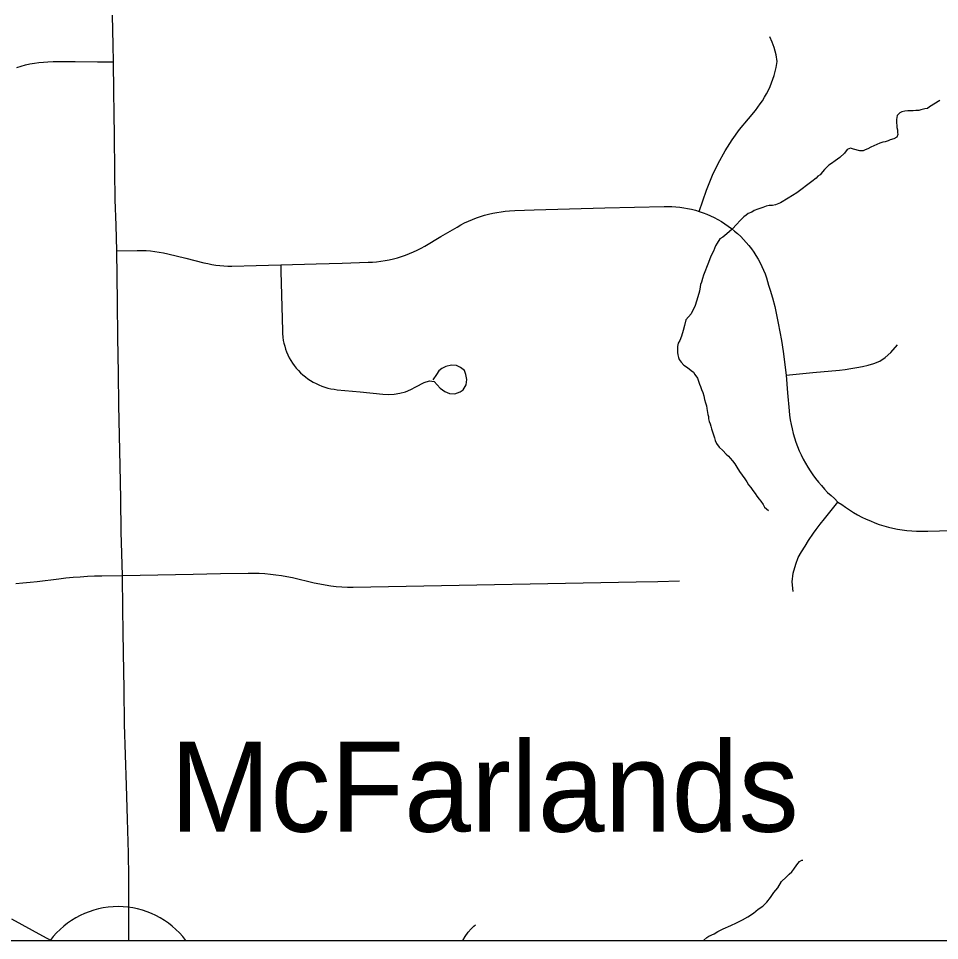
# Model space of a CAD drawing. Extents: x 103424 to 286016, y 38711 to 110967.
# Drawn here: x 108261 to 112556, y 38711 to 43011 of the extents above; entities that cross this region are included whole.
import ezdxf

# ---------------------------------------------------------------- set-up
doc = ezdxf.new("R2010")
doc.units = 0
for name, color, linetype in [('GM_X_Corporation', 7, 'Continuous'), ('GM_X_County_Road', 7, 'Continuous'), ('GM_X_Minor_River', 7, 'Continuous'), ('GM_X_State_Route', 7, 'Continuous'), ('GM_X_Township_Road', 7, 'Continuous'), ('GM_X_Unincorporated_Text', 7, 'Continuous'), ('GM_X_US_Shield', 7, 'Continuous')]:
    doc.layers.add(name, color=color, linetype=linetype)

msp = doc.modelspace()

# ---------------------------------------------------------------- linework, layer by layer
at = {"layer": 'GM_X_Corporation'}
for points in [[(103423.7, 96534.8), (103423.7, 38711.2), (175679.7, 38711.2), (175679.7, 110967.2), (119699, 110967.2), (119716.9, 106542.5), (119719.8, 106322.8), (119720.8, 106006.3), (119709.7, 99445.7), (119706.4, 99064.2), (119663.9, 96690), (117026.4, 96688.2), (115542.1, 96665), (105081.7, 96574.5)], [(103423.7, 43132.7), (103423.7, 38711.2), (119963.5, 38711.2), (119934.2, 43543), (116952, 43470.9), (108691.3, 43264.4)]]:
    msp.add_lwpolyline(points, close=True, dxfattribs=at)
at = {"layer": 'GM_X_County_Road'}
msp.add_lwpolyline([(108228, 38812.2), (108373.1, 38733.4), (108414, 38711.2)], dxfattribs=at)
at = {"layer": 'GM_X_Minor_River'}
for points in [[(112556.9, 42628.6), (112508.9, 42599.5), (112499, 42591.3), (112486.9, 42589.1), (112468.8, 42584.7), (112458.8, 42582.6), (112444.6, 42582.3), (112432.6, 42580.1), (112420.5, 42579.9), (112408.3, 42579.7), (112394.2, 42579.5), (112380.2, 42575.2), (112370.2, 42571), (112358.3, 42558.7), (112354.5, 42540.4), (112354.8, 42524.3), (112357, 42512.2), (112357.2, 42502.1), (112359.4, 42492), (112359.6, 42479.9), (112361.8, 42469.8), (112355.9, 42457.6), (112341.9, 42449.3), (112325.9, 42445), (112315.9, 42440.8), (112301.8, 42436.5), (112291.7, 42434.3), (112277.7, 42430.1), (112263.7, 42423.8), (112249.7, 42417.5), (112235.6, 42411.2), (112221.7, 42402.9), (112209.6, 42398.7), (112199.6, 42394.4), (112183.5, 42394.2), (112155.1, 42401.8), (112140.9, 42405.6), (112124.8, 42399.3), (112113, 42382.9), (112091.2, 42362.4), (112069.2, 42347.9), (112051.3, 42335.4), (112039.3, 42327.2), (112019.5, 42306.6), (112009.5, 42296.4), (111999.7, 42282.1), (111987.7, 42275.8), (111979.8, 42265.6), (111959.9, 42251.1), (111890.1, 42197.4), (111850.2, 42172.5), (111814.2, 42151.7), (111790.2, 42141.2), (111776.1, 42139), (111762, 42138.8), (111747.9, 42136.5), (111731.9, 42130.2), (111707.8, 42121.7), (111691.7, 42115.4), (111679.8, 42107.1), (111663.7, 42100.8), (111653.7, 42094.5), (111643.8, 42086.3), (111623.9, 42067.8), (111610.1, 42051.4), (111588.3, 42028.8), (111564.4, 42006.2), (111544.5, 41991.7), (111530.5, 41983.4), (111518.8, 41963), (111510.9, 41950.8), (111501.2, 41926.4), (111489.5, 41901.9), (111477.9, 41873.5), (111454.7, 41814.5), (111450.9, 41798.3), (111445.1, 41782), (111441.3, 41769.8), (111439.4, 41759.7), (111435.7, 41739.4), (111428.1, 41713), (111416.7, 41672.4), (111397.2, 41633.7), (111373.4, 41605.1), (111365.8, 41578.7)], [(111365.8, 41578.7), (111360.1, 41556.4), (111352.5, 41530), (111344.8, 41509.6), (111336.9, 41497.4), (111333.1, 41481.2), (111333.4, 41463), (111333.6, 41452.9), (111335.8, 41442.8), (111338, 41430.7), (111342.2, 41420.7), (111350.5, 41408.7), (111362.8, 41394.8), (111381.2, 41383), (111397.6, 41369.1), (111407.8, 41361.2), (111414, 41351.2), (111426.4, 41333.2), (111432.8, 41315.1), (111437, 41305.1), (111441.2, 41295.1), (111445.5, 41281), (111451.7, 41266.9), (111456.1, 41250.8), (111460.4, 41234.8), (111464.7, 41218.7), (111468.9, 41204.6), (111471.2, 41192.5), (111475.7, 41164.3), (111477.9, 41154.2), (111478, 41144.1), (111482.3, 41132.1), (111486.5, 41120), (111488.7, 41110), (111492.9, 41097.9), (111497.2, 41083.8), (111501.5, 41069.8), (111505.7, 41055.7), (111510, 41043.7), (111516.3, 41029.6), (111528.7, 41011.6), (111545.1, 40995.7), (111561.5, 40979.8), (111571.8, 40969.9), (111580, 40959.9), (111590.3, 40948), (111600.6, 40934), (111611, 40918), (111623.4, 40898), (111635.8, 40882.1), (111648.2, 40864.1), (111656.5, 40850.1), (111664.8, 40836.1), (111675.1, 40824.1), (111685.4, 40810.2), (111695.7, 40796.2), (111704, 40784.2), (111714.3, 40770.2), (111722.6, 40760.3), (111732.9, 40744.3), (111739.2, 40732.2), (111749.4, 40724.3), (111757.6, 40716.4)], [(111453.9, 38711.2), (111456.3, 38713.3), (111470.2, 38725.7), (111480.2, 38731.9), (111504.2, 38742.4), (111522.2, 38752.8), (111546.2, 38765.3), (111582.3, 38782.1), (111608.3, 38794.6), (111636.3, 38807.2), (111662.3, 38821.8), (111688.3, 38838.4), (111710.1, 38856.9), (111732.1, 38871.4), (111749.9, 38889.9), (111767.7, 38912.4), (111783.5, 38934.9), (111801.3, 38957.4), (111819, 38986), (111840.8, 39006.6), (111854.7, 39020.9), (111866.6, 39031.2), (111876.5, 39043.5), (111890.3, 39063.9), (111902.1, 39080.3), (111914.1, 39086.5), (111918.2, 39086.6)], [(110333, 38711.2), (110344.2, 38729.4), (110357.9, 38749.8), (110371.8, 38766.2), (110383.7, 38778.5), (110391.7, 38784.7)]]:
    msp.add_lwpolyline(points, dxfattribs=at)
at = {"layer": 'GM_X_State_Route'}
msp.add_lwpolyline([(108776.1, 38711.2), (108775.8, 38730), (108775.3, 38895), (108774.9, 39006.8), (108774.5, 39118.6), (108769.5, 39276.6), (108764.6, 39434.6), (108760.1, 39577.6), (108755.6, 39720.6), (108753.1, 39885.6), (108750.6, 40050.6), (108749, 40153.1), (108747.5, 40255.6), (108745.7, 40413.9), (108743.2, 40515.7), (108740.6, 40617.5), (108737.6, 40771.4), (108734.6, 40925.3), (108732.1, 41066.6), (108729.5, 41207.8), (108726.9, 41357.5), (108724.7, 41522.6), (108722.6, 41687.6), (108721, 41807.7), (108719.5, 41927.7), (108717, 42046.4), (108712.3, 42165.6), (108710.6, 42299), (108708.5, 42464), (108707.2, 42567.4), (108705.9, 42670.7), (108704.7, 42808.3), (108703, 42886), (108699, 43027)], dxfattribs=at)
at = {"layer": 'GM_X_Township_Road'}
for points in [[(111434.8, 42111.5), (111469.7, 42210.6), (111496.9, 42281), (111523.2, 42335.3), (111556.2, 42393.9), (111588.5, 42444.8), (111622.7, 42493.5), (111664.3, 42543.5), (111696.8, 42582.6), (111708.4, 42597.1), (111719.5, 42612.2), (111729.8, 42627.6), (111739.6, 42643.5), (111748.9, 42659.7), (111757.5, 42676.2), (111765.3, 42693.2), (111772.6, 42710.3), (111778.9, 42727.8), (111784.9, 42745.6), (111790, 42763.5), (111794.5, 42781.6), (111798.3, 42810.3), (111794.7, 42841.2), (111785.3, 42875.1), (111775.3, 42900.9), (111763.8, 42924.7)], [(108253.4, 42783), (108273.6, 42789), (108294, 42794.2), (108314.6, 42798.7), (108335.2, 42802.5), (108356.1, 42805.5), (108377.3, 42807.9), (108398.2, 42809.5), (108422.6, 42810.4), (108526, 42809.6), (108629.4, 42808.8), (108704.7, 42808.3)], [(108719.5, 41927.7), (108815.1, 41929.4), (108855.9, 41928.6), (108876.3, 41927.1), (108896.7, 41924.8), (108917, 41921.8), (108937.2, 41918), (108957.1, 41913.5), (109041.5, 41892.8), (109125.9, 41872), (109144.1, 41867.9), (109162.4, 41864.3), (109180.8, 41861.4), (109199.4, 41859.1), (109218.1, 41857.4), (109236.7, 41856.4), (109255.3, 41856.1), (109369.5, 41859.1), (109483.7, 41862.2), (109648.7, 41867), (109769.9, 41870.6), (109891.2, 41874.1), (109911, 41875.1), (109930.9, 41876.8), (109950.6, 41879.1), (109970.2, 41882.1), (109989.6, 41885.9), (110009, 41890.3), (110028.1, 41895.5), (110047, 41901.2), (110065.9, 41907.8), (110084.2, 41914.9), (110102.4, 41922.7), (110120.5, 41931.2), (110138.1, 41940.3), (110155.2, 41950), (110230.8, 41994.3), (110306.3, 42038.6), (110323.7, 42048.4), (110341.3, 42057.4), (110359.2, 42065.9), (110377.6, 42073.7), (110395.9, 42080.9), (110414.8, 42087.3), (110433.7, 42093.2), (110452.8, 42098.3), (110472.2, 42102.7), (110491.6, 42106.5), (110511.2, 42109.6), (110530.9, 42111.9), (110550.8, 42113.5), (110574.8, 42114.9), (110665, 42118.4), (110830, 42122.9), (110995, 42127.4), (111133.1, 42131.1), (111271.2, 42134.8), (111307.9, 42134.5), (111326.6, 42133.3), (111344.9, 42131.4), (111363, 42128.7), (111381.2, 42125.5), (111399.3, 42121.5), (111417.2, 42116.9), (111434.8, 42111.5), (111452.9, 42105.4), (111470.5, 42098.5), (111488.1, 42090.9), (111505.3, 42082.7), (111522.1, 42073.7), (111538.5, 42064.2), (111554.6, 42054), (111570.4, 42043.2), (111585.5, 42031.8), (111600.4, 42019.8), (111613.9, 42007.8), (111628.5, 41994.1), (111641.9, 41980.4), (111654.4, 41966.3), (111666.8, 41951.7), (111678.3, 41936.5), (111689.4, 41921), (111699.7, 41905), (111709.5, 41888.6), (111718.6, 41872), (111726.9, 41854.9), (111734.7, 41837.5), (111742, 41819.8), (111748.3, 41801.8), (111754, 41783.7), (111758.6, 41767.9), (111766.5, 41743.4), (111777, 41708.4), (111787, 41667.9), (111795.5, 41628.9), (111803.5, 41589.9), (111811, 41550.5), (111819, 41509), (111827, 41457.9), (111840.9, 41348), (111847.5, 41265), (111854.2, 41181.8), (111856.5, 41160.5), (111859.7, 41139.2), (111863.5, 41118.1), (111868.3, 41097.1), (111873.6, 41076.4), (111879.6, 41055.7), (111886.4, 41035.3), (111893.9, 41015.2), (111901.9, 40995.4), (111911, 40975.8), (111920.3, 40956.5), (111930.6, 40937.6), (111941.4, 40919), (111952.8, 40900.9), (111964.8, 40883.1), (111977.6, 40865.8), (111991, 40848.9), (112004.8, 40832.5), (112019.2, 40816.5), (112034, 40801.1), (112049.6, 40786.2), (112065.5, 40771.8), (112082.1, 40756), (112099.4, 40744.4), (112117.3, 40731.5), (112135.7, 40719.1), (112154.5, 40707.5), (112173.7, 40696.4), (112193.3, 40686.1), (112213.2, 40676.5), (112233.3, 40667.7), (112253.9, 40659.5), (112274.8, 40652), (112295.7, 40645.4), (112317.1, 40639.4), (112338.5, 40634.3), (112360.2, 40629.9), (112382.1, 40626.2), (112403.9, 40623.3), (112426.1, 40621.3), (112448, 40620), (112470.1, 40619.5), (112500.9, 40620), (112665.9, 40624.3)], [(109483.7, 41862.2), (109485, 41830.6), (109486.3, 41776.9), (109489, 41666.6), (109491.7, 41556.4), (109492.4, 41541.3), (109493.8, 41525.3), (109495.7, 41509.9), (109498.2, 41497.2), (109502.4, 41483.2), (109506.8, 41469), (109510.9, 41455.9), (109516.7, 41442.4), (109523.5, 41429.2), (109530.8, 41416.4), (109538.5, 41404), (109547.1, 41392), (109556.4, 41380.5), (109566.2, 41369.5), (109576.5, 41358.9), (109587.3, 41348.9), (109598.7, 41339.6), (109610.5, 41330.8), (109622.8, 41322.6), (109635.4, 41315.1), (109648.5, 41308.1), (109661.8, 41302), (109675.7, 41296.5), (109689.5, 41291.7), (109703.6, 41287.6), (109718, 41284.3), (109732.6, 41281.7), (109747.2, 41279.9), (109853.8, 41269.3), (109960.4, 41258.8), (109987, 41257.6), (110013.5, 41259.1), (110039.6, 41263.5), (110065.1, 41270.6), (110090, 41280.4), (110113.4, 41292.6), (110152.9, 41313.7), (110177.9, 41321.8), (110198.9, 41317.8), (110212.6, 41302.4), (110227.2, 41287.1), (110249, 41271), (110271.5, 41262.1), (110295.8, 41261.3), (110320, 41270.1), (110334.5, 41279.8), (110348.2, 41303.3), (110352.2, 41326.7), (110347.4, 41350.9), (110340.1, 41370.2), (110321.6, 41383.1), (110303, 41392), (110280.4, 41393.6), (110253, 41388.8), (110234.4, 41379.1), (110221.5, 41368.6), (110209.4, 41350.1), (110193.3, 41325.8)], [(111840.9, 41348), (111964.8, 41359.7), (112088.6, 41371.4), (112115.8, 41374.4), (112142.8, 41378.2), (112169.7, 41382.9), (112196.4, 41388.3), (112223.1, 41394.4), (112249.5, 41401.4), (112277.4, 41413.5), (112302.2, 41429.9), (112328.2, 41452.9), (112359.3, 41489.1)], [(111872.5, 40339.5), (111869.2, 40384.5), (111873.4, 40423.8), (111885.5, 40466.8), (111896.9, 40497), (111912.3, 40524.1), (111928.4, 40550.8), (111945.3, 40577.1), (111968, 40610.6), (111980.6, 40628.3), (111999.5, 40653.3), (112018.6, 40677.8), (112082.1, 40756)], [(108745.7, 40413.9), (108910.7, 40416.9), (109075.8, 40419.8), (109203.6, 40422.1), (109331.5, 40424.3), (109383.5, 40423.7), (109409.5, 40422.3), (109435.6, 40420.2), (109461.6, 40417.3), (109487.2, 40413.6), (109512.9, 40409.2), (109538.6, 40404.1), (109564, 40398.2), (109614.3, 40385), (109639.8, 40379.1), (109665.4, 40374), (109691.1, 40369.5), (109717, 40365.8), (109743, 40362.8), (109768.9, 40360.7), (109794.8, 40359.2), (109821, 40358.5), (109986, 40361.7), (110151.1, 40364.9), (110316.1, 40368.1), (110481.1, 40371.3), (110646.2, 40374.5), (110811.2, 40377.8), (110976.2, 40381), (111141.3, 40384.2), (111242.3, 40386.1), (111343.4, 40388.1)], [(108248.6, 40376.2), (108282, 40378.7), (108315.2, 40381.9), (108348.7, 40385.8), (108448.7, 40398.2), (108481.9, 40402), (108515.4, 40405.3), (108548.6, 40407.9), (108582.1, 40410), (108615.6, 40411.4), (108649.3, 40412.3), (108745.7, 40413.9)]]:
    msp.add_lwpolyline(points, dxfattribs=at)
at = {"layer": 'GM_X_US_Shield'}
msp.add_line((108408.7, 38711.2), (109041.7, 38711.2), dxfattribs=at)
msp.add_arc((108725.2, 38474.3), 395.3, 36.8073, 143.1927, dxfattribs=at)

# ---------------------------------------------------------------- texts
at = {"layer": 'GM_X_Unincorporated_Text'}
msp.add_text('McFarlands', height=419.6, rotation=0, dxfattribs=at).set_placement((108968.2, 39218.8))

doc.saveas('drawing.dxf')
